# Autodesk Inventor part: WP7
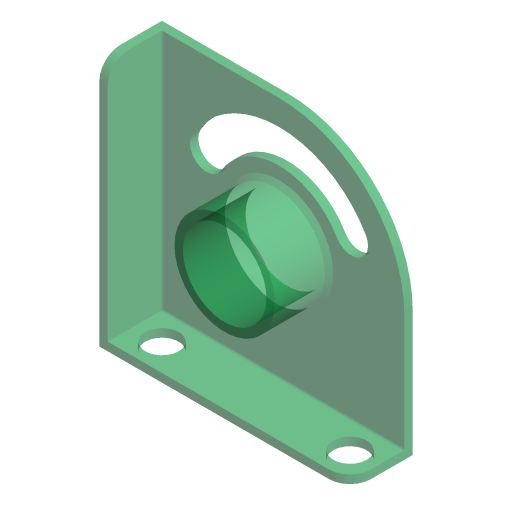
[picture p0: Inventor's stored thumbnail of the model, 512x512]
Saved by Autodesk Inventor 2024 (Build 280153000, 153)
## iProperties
Company: ATC
Shininess: 0.0
Length Units: 11269
Angle Units: 11279
Time Units: 11290
Mass Units: 11283
Length Display Precision: 3
Angle Display Precision: 2
Compacted: True
Created: 2023-03
Part Number: WP7
Document SubType Name: Modeling
Designer: Andrzej Jaskulski
Material: Kurs-AJ
Density: 1 g/cm^3
Appearance: Przezroczyste - zielone 1
Checked By: A.J.
Engr Approved By: Andrzej Jaskulski
Mfg Approved By: Andrzej Jaskulski
Authority: A.J.
Density: 0.0
Volumn: 0.0
Area: 0.0
PropertySet Name: Model Information
Control State: 0
Master: False
Checked Out: False
Title: A.J.: Kurs R2024-MEP
Author: Andrzej Jaskulski
Revision Number: 1/24
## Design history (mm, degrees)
node "Extrusion1" dims "d1" = 15, "d2" = 0
  sketch "Sketch1"
    geometry: L1 (0, 0)-(60, 0); L2 (60, 0)-(60, 60); L3 (60, 60)-(0, 60); L4 (0, 60)-(0, 0)
    constraints: 8 end point, 2 parallel, 2 perpendicular, 1 horizontal, 1 other
    dimensions: "d0" = 60 distance of L1.start L1.end
node "Hole1" dims "d5" = 20, "d6" = 4, "d7" = 2, "d8" = 60 deg, "d9" = 8, "d10" = 118 deg
  sketch "Sketch3"
    geometry: L1 (0, 0)-(60, 0) reference; L2 (0, 60)-(0, 0) reference; 1 further point
    dimensions: "d3" = 30 distance from line of L1 point (30, 30); "d4" = 30 distance from line of L2 point (30, 30)
node "Fillet1" dims "d12" = 5
node "Fillet2" dims "d13" = 30
node "Shell2" dims "d14" = 2
node "Hole2" dims "d17" = 8, "d18" = 4, "d19" = 2, "d20" = 60 deg, "d21" = 8, "d22" = 118 deg
  sketch "Sketch4"
    geometry: L1 (58, 0)-(58, -8) reference; L2 (0, -13)-(0, 0) reference; L3 (53, -13)-(0, -13) reference; L4 (0, -6.5)-(58, -6.5); 2 further points
    constraints: 3 point on line, 2 end point, 1 midpoint, 1 parallel
    dimensions: "d15" = 6.5 distance from line of L2 point (6.5, -6.5); "d16" = 6.5 distance from line of L1 point (51.5, -6.5); "d33" = 6.5 distance between parallel lines of L3 L4; "d34" = 45 distance of point (51.5, -6.5) point (6.5, -6.5)
node "Extrusion2" dims "d28" = 15, "d29" = 0
  sketch "Sketch5"
    geometry: L1 (-30, 60)-(0, 60) reference; L2 (-30, 30)-(-30, 63); C1 r 10 at (-30, 30) reference; A1 r 16 centre (-30, 30) between (-16.144, 38) and (-43.856, 38); A2 r 24 centre (-30, 30) between (-9.215, 42) and (-50.785, 42); A3 r 4 centre (-47.321, 40) between (-50.785, 42) and (-43.856, 38); A4 r 4 centre (-12.679, 40) between (-16.144, 38) and (-9.215, 42)
    constraints: 8 point on circle, 4 centre point, 2 coincident, 2 end point, 2 tangent, 1 perpendicular
    dimensions: "d26" = 16 radius of A1; "d27" = 24 radius of A2
node "Fillet3" dims "d30" = 0.5
node "Chamfer1" dims "d31" = 1, "d32" = 1, "d35" = 45 deg
node "Bryła1"
node "Korpusy bryłowe"
node "Korpusy powierzchniowe"
